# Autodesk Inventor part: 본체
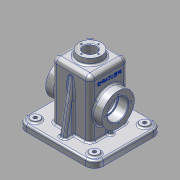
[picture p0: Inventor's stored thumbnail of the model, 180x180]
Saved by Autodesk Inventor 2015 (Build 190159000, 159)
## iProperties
Created: 2016-02
Part Number: 본체
Material: 알루미늄 6061
Document SubType Name: Modeling
Designer: Administrator
Density: 2.7 g/cm^3
Appearance: 알루미늄 - 평지
Mass: 883.249 g
Surface Area: 914.012 cm^2
Volume: 327.129 cm^3
Author: Administrator
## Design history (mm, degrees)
sketch "스케치7"
  geometry: L1 (32.5, 32.5)-(-32.5, 32.5); L2 (-32.5, 32.5)-(-32.5, -32.5); L3 (-32.5, -32.5)-(32.5, -32.5); L4 (32.5, -32.5)-(32.5, 32.5); L5 (32.5, 32.5)-(-32.5, -32.5); L6 (-32.5, 32.5)-(32.5, -32.5); 1 further point
  constraints: 12 end point, 2 midpoint, 2 parallel, 2 perpendicular, 1 horizontal
  dimensions: "d20" = 65 distance of L2.end L3.end
extrude "돌출6" new body sketch "스케치7" distance "d21" = 110; taper "d22" = 0 deg
fillet "모깎기2" dims "d23" = 8
fillet "모깎기3" dims "d24" = 8
feature "쉘1" dims "d25" = 5
sketch "스케치8"
  geometry: C1 r 20 at (0, 0); 1 further point
  constraints: 1 centre point, 1 coincident
  dimensions: "d26" = 40 diameter of C1
extrude "돌출7" join sketch "스케치8" distance "d27" = 10; taper "d28" = 0 deg
feature "면 기울기2" dims angle "d29" = 5 deg
sketch "스케치9"
  geometry: L1 (65, 57.5)-(-65, 57.5); L2 (-65, 57.5)-(-65, -57.5); L3 (-65, -57.5)-(65, -57.5); L4 (65, -57.5)-(65, 57.5); L5 (65, 57.5)-(-65, -57.5); L6 (-65, 57.5)-(65, -57.5); L7 (27.5, -24.5)-(27.5, 24.5) reference; L8 (24.5, 27.5)-(-24.5, 27.5) reference; L9 (-27.5, 24.5)-(-27.5, -24.5) reference; L10 (-24.5, -27.5)-(24.5, -27.5) reference; L11 (24.5, -32.5)-(-24.5, -32.5) reference; L12 (-32.5, -24.5)-(-32.5, 24.5) reference; L13 (-24.5, 32.5)-(24.5, 32.5) reference; L14 (32.5, 24.5)-(32.5, -24.5) reference; A1 r 3 centre (24.5, -24.5) between (24.5, -27.5) and (27.5, -24.5) reference; A2 r 3 centre (24.5, 24.5) between (27.5, 24.5) and (24.5, 27.5) reference; A3 r 3 centre (-24.5, 24.5) between (-24.5, 27.5) and (-27.5, 24.5) reference; A4 r 3 centre (-24.5, -24.5) between (-27.5, -24.5) and (-24.5, -27.5) reference; A5 r 8 centre (24.5, -24.5) between (24.5, -32.5) and (32.5, -24.5) reference; A6 r 8 centre (-24.5, -24.5) between (-32.5, -24.5) and (-24.5, -32.5) reference; A7 r 8 centre (-24.5, 24.5) between (-24.5, 32.5) and (-32.5, 24.5) reference; A8 r 8 centre (24.5, 24.5) between (32.5, 24.5) and (24.5, 32.5) reference; 1 further point
  constraints: 12 end point, 2 midpoint, 2 parallel, 1 horizontal, 1 perpendicular
  dimensions: "d30" = 130 distance of L2.end L3.end; "d31" = 115 distance of L1.end L2.end
extrude "돌출8" join sketch "스케치9" distance "d32" = 13; taper "d33" = 0 deg
fillet "모깎기4" dims "d34" = 15
sketch "스케치11"
  geometry: L1 (110, 24.5)-(110, 20) reference; L2 (110, 20)-(120, 19.125) reference; L3 (120, 19.125)-(120, -19.125) reference; L4 (120, -19.125)-(110, -20) reference; L5 (110, -20)-(110, -24.5) reference; L6 (102, -32.5)-(13, -32.5) reference; L7 (13, -57.5)-(0, -57.5) reference; L8 (13, 57.5)-(13, 32.5) reference; L9 (0, -27.5)-(102, -27.5) reference; L10 (105, -24.5)-(105, 24.5) reference; L11 (102, 27.5)-(0, 27.5) reference; L12 (13, -32.5)-(13, -57.5) reference; L13 (0, 57.5)-(13, 57.5) reference; L14 (13, 32.5)-(102, 32.5) reference; L15 (98.069, 32.5)-(13, 47.5); L16 (13, 47.5)-(13, 32.5); L17 (13, 32.5)-(98.069, 32.5); L18 (0, 0)-(66.088, 0); L19 (13, -32.5)-(98.069, -32.5); L20 (98.069, -32.5)-(13, -47.5); L21 (13, -47.5)-(13, -32.5); L22 (0, -57.5)-(0, -27.5) reference; L23 (0, 27.5)-(0, 57.5) reference; A1 r 8 centre (102, 24.5) between (110, 24.5) and (102, 32.5) reference; A2 r 8 centre (102, -24.5) between (102, -32.5) and (110, -24.5) reference; A3 r 3 centre (102, -24.5) between (102, -27.5) and (105, -24.5) reference; A4 r 3 centre (102, 24.5) between (105, 24.5) and (102, 27.5) reference
  constraints: 14 end point, 3 symmetric about line, 2 collinear, 1 horizontal, 1 perpendicular, 1 vertical
  dimensions: "d38" = 10 deg angle of L13 L15; "d39" = 10 distance from line of L13 L15.end
extrude "돌출10" join sketch "스케치11" stored distance "d40" = 10; taper "d41" = 0 deg
sketch "스케치12"
  geometry: L1 (65, 42.5)-(65, -42.5) reference; L2 (50, -57.5)-(-50, -57.5) reference; L3 (-65, -42.5)-(-65, 42.5) reference; L4 (-50, 57.5)-(50, 57.5) reference; L5 (24.5, 27.5)-(-24.5, 27.5) reference; L6 (-27.5, 24.5)-(-27.5, -24.5) reference; L7 (-24.5, -27.5)-(24.5, -27.5) reference; L8 (27.5, -24.5)-(27.5, 24.5) reference; L9 (60, -42.5)-(60, 42.5); L10 (50, 52.5)-(-50, 52.5); L11 (-60, 42.5)-(-60, -42.5); L12 (-50, -52.5)-(50, -52.5); A1 r 15 centre (50, 42.5) between (65, 42.5) and (50, 57.5) reference; A2 r 15 centre (50, -42.5) between (50, -57.5) and (65, -42.5) reference; A3 r 15 centre (-50, -42.5) between (-65, -42.5) and (-50, -57.5) reference; A4 r 15 centre (-50, 42.5) between (-50, 57.5) and (-65, 42.5) reference; A5 r 3 centre (24.5, 24.5) between (27.5, 24.5) and (24.5, 27.5) reference; A6 r 3 centre (-24.5, 24.5) between (-24.5, 27.5) and (-27.5, 24.5) reference; A7 r 3 centre (-24.5, -24.5) between (-27.5, -24.5) and (-24.5, -27.5) reference; A8 r 3 centre (24.5, -24.5) between (24.5, -27.5) and (27.5, -24.5) reference; A9 r 10 centre (50, 42.5) between (60, 42.5) and (50, 52.5); A10 r 10 centre (-50, 42.5) between (-50, 52.5) and (-60, 42.5); A11 r 10 centre (-50, -42.5) between (-60, -42.5) and (-50, -52.5); A12 r 10 centre (50, -42.5) between (50, -52.5) and (60, -42.5); 1 further point
  constraints: 8 end point, 8 point on circle, 4 centre point, 7 other
  dimensions: "d42" = 5 distance between parallel lines of L1 L9
extrude "돌출11" cut sketch "스케치12" distance "d43" = 2; taper "d44" = 0 deg
node "작업 평면1"
sketch "스케치13"
  geometry: L1 (24.5, -47)-(24.5, -102); C1 r 27.5 at (24.5, -47)
  constraints: 2 end point, 1 centre point, 1 vertical
  dimensions: "d46" = 55 distance of L1.start L1.end; "d47" = 55 diameter of C1
extrude "돌출12" join sketch "스케치13" stored distance "d48" = 2; taper "d49" = 0 deg
sketch "스케치14"
  geometry: L1 (-24.5, 110)-(-20, 110) reference; L2 (-20, 110)-(-19.125, 120) reference; L3 (-19.125, 120)-(19.125, 120) reference; L4 (19.125, 120)-(20, 110) reference; L5 (20, 110)-(24.5, 110) reference; L6 (32.5, 102)-(32.5, 82.5) reference; L7 (32.5, 82.5)-(47.5, 82.5) reference; L8 (47.5, 82.5)-(47.5, 27.5) reference; L9 (47.5, 27.5)-(32.5, 27.5) reference; L10 (32.5, 27.5)-(32.5, 13) reference; L11 (32.5, 13)-(65, 13) reference; L12 (65, 13)-(65, 2) reference; L13 (65, 2)-(60, 2) reference; L14 (60, 2)-(60, 0) reference; L15 (60, 0)-(27.5, 0) reference; L16 (27.5, 0)-(27.5, 102) reference; L17 (24.5, 105)-(-24.5, 105) reference; L18 (-27.5, 102)-(-27.5, 0) reference; L19 (-27.5, 0)-(-60, 0) reference; L20 (-60, 0)-(-60, 2) reference; L21 (-60, 2)-(-65, 2) reference; L22 (-65, 2)-(-65, 13) reference; L23 (-65, 13)-(-32.5, 13) reference; L24 (-32.5, 13)-(-32.5, 102) reference; L25 (32.5, 13)-(32.5, 37.5); L26 (32.5, 13)-(37.5, 13); L27 (37.5, 13)-(37.5, 37.5); L28 (37.5, 37.5)-(32.5, 37.5); A1 r 8 centre (-24.5, 102) between (-24.5, 110) and (-32.5, 102) reference; A2 r 8 centre (24.5, 102) between (32.5, 102) and (24.5, 110) reference; A3 r 3 centre (24.5, 102) between (27.5, 102) and (24.5, 105) reference; A4 r 3 centre (-24.5, 102) between (-24.5, 105) and (-27.5, 102) reference; 2 further points
  constraints: 8 end point, 2 collinear, 2 point on line, 1 parallel, 1 perpendicular
  dimensions: "d73" = 10 distance between parallel lines of L16 L27; "d74" = 10 distance between parallel lines of L28 L9
extrude "돌출13" join sketch "스케치14" stored distance "d51" = 6; taper "d52" = 0 deg
sketch "스케치15"
  geometry: L1 (-65, -42.5)-(-65, 42.5) reference; L2 (-50, 57.5)-(50, 57.5) reference; L3 (65, 42.5)-(65, -42.5) reference; L4 (50, -57.5)-(-50, -57.5) reference; L5 (-24.5, -27.5)-(24.5, -27.5) reference; L6 (27.5, -24.5)-(27.5, 24.5) reference; L7 (24.5, 27.5)-(-24.5, 27.5) reference; L8 (-27.5, 24.5)-(-27.5, -24.5) reference; L9 (-32.5, -24.5)-(-32.5, 24.5) reference; L10 (-24.5, 32.5)-(-5, 32.5) reference; L11 (-5, 32.5)-(-5, 47.5) reference; L12 (-5, 47.5)-(5, 47.5) reference; L13 (5, 47.5)-(5, 32.5) reference; L14 (5, 32.5)-(24.5, 32.5) reference; L15 (32.5, 24.5)-(32.5, 3) reference; L16 (32.5, 3)-(37.5, 3) reference; L17 (37.5, -3)-(32.5, -3) reference; L18 (32.5, -3)-(32.5, -24.5) reference; L19 (24.5, -32.5)-(5, -32.5) reference; L20 (5, -32.5)-(5, -47.5) reference; L21 (5, -47.5)-(-5, -47.5) reference; L22 (-5, -47.5)-(-5, -32.5) reference; L23 (-5, -32.5)-(-24.5, -32.5) reference; L24 (37.5, 3)-(37.5, -3) reference; C1 r 7.5 at (-50, -42.5); C2 r 7.5 at (-50, 42.5); C3 r 7.5 at (50, 42.5); C4 r 7.5 at (50, -42.5); A1 r 15 centre (-50, 42.5) between (-50, 57.5) and (-65, 42.5) reference; A2 r 15 centre (50, 42.5) between (65, 42.5) and (50, 57.5) reference; A3 r 15 centre (50, -42.5) between (50, -57.5) and (65, -42.5) reference; A4 r 15 centre (-50, -42.5) between (-65, -42.5) and (-50, -57.5) reference; A5 r 3 centre (-24.5, -24.5) between (-27.5, -24.5) and (-24.5, -27.5) reference; A6 r 3 centre (24.5, -24.5) between (24.5, -27.5) and (27.5, -24.5) reference; A7 r 3 centre (24.5, 24.5) between (27.5, 24.5) and (24.5, 27.5) reference; A8 r 3 centre (-24.5, 24.5) between (-24.5, 27.5) and (-27.5, 24.5) reference; A9 r 8 centre (-24.5, -24.5) between (-32.5, -24.5) and (-24.5, -32.5) reference; A10 r 8 centre (-24.5, 24.5) between (-24.5, 32.5) and (-32.5, 24.5) reference; A11 r 8 centre (24.5, 24.5) between (32.5, 24.5) and (24.5, 32.5) reference; A12 r 8 centre (24.5, -24.5) between (24.5, -32.5) and (32.5, -24.5) reference; 1 further point
  constraints: 4 centre point, 4 coincident, 3 equal radius
  dimensions: "d53" = 15 diameter of C1
extrude "돌출14" join sketch "스케치15" distance "d54" = 3; taper "d55" = 0 deg
sketch "스케치16"
  geometry: L1 (25.5, -70)-(74.5, -70) reference; L2 (77.5, -67)-(77.5, -18) reference; L3 (74.5, -15)-(25.5, -15) reference; L4 (22.5, -18)-(22.5, -67) reference; L5 (17.5, -67)-(17.5, -18) reference; L6 (25.5, -10)-(45, -10) reference; L7 (45, -10)-(45, 4.471) reference; L8 (45, 4.471)-(55, 4.471) reference; L9 (55, 4.471)-(55, -10) reference; L10 (55, -10)-(74.5, -10) reference; L11 (82.5, -18)-(82.5, -39.5) reference; L12 (82.5, -39.5)-(87.5, -39.5) reference; L13 (87.5, -45.5)-(82.5, -45.5) reference; L14 (82.5, -45.5)-(82.5, -67) reference; L15 (74.5, -75)-(55, -75) reference; L16 (55, -75)-(55, -89.471) reference; L17 (55, -89.471)-(45, -89.471) reference; L18 (45, -89.471)-(45, -75) reference; L19 (45, -75)-(25.5, -75) reference; L20 (87.5, -39.5)-(87.5, -45.5) reference; C1 r 7.5 at (100, 0) reference; C2 r 7.5 at (0, -85) reference; C3 r 7.5 at (0, 0) reference; C4 r 7.5 at (100, -85) reference; A1 r 3 centre (25.5, -67) between (22.5, -67) and (25.5, -70) reference; A2 r 3 centre (74.5, -67) between (74.5, -70) and (77.5, -67) reference; A3 r 3 centre (74.5, -18) between (77.5, -18) and (74.5, -15) reference; A4 r 3 centre (25.5, -18) between (25.5, -15) and (22.5, -18) reference; A5 r 8 centre (25.5, -67) between (17.5, -67) and (25.5, -75) reference; A6 r 8 centre (25.5, -18) between (25.5, -10) and (17.5, -18) reference; A7 r 8 centre (74.5, -18) between (82.5, -18) and (74.5, -10) reference; A8 r 8 centre (74.5, -67) between (74.5, -75) and (82.5, -67) reference; 1 further point
hole "구멍1" sketch "스케치16" at (0, 0), (100, 0), (100, -85), (0, -85) diameter "d56" = 6; stored, may be unused: countersink angle "d60" = 90 deg, drill point angle "d62" = 118 deg; dims "d57" = 6, "d58" = 4, "d59" = 2, "d61" = 8
hole "구멍2" diameter "d65" = 30; stored, may be unused: countersink angle "d69" = 90 deg, drill point angle "d71" = 118 deg; dims "d63" = 10, "d64" = 10, "d66" = 6, "d67" = 35, "d68" = 17, "d70" = 8
fillet "모깎기11" dims "d80" = 3
hole "구멍3" diameter "d83" = 21; stored, may be unused: countersink angle "d87" = 90 deg, drill point angle "d89" = 118 deg; dims "d81" = 10, "d82" = 10, "d84" = 6, "d85" = 35, "d86" = 17, "d88" = 8
fillet "모깎기12" dims "d90" = 3
chamfer "모따기1" distance "d91" = 1; stored, may be unused: second distance "d92" = 2, angle "d93" = 45 deg
fillet "모깎기13" dims "d94" = 0.3
fillet "모깎기14" dims "d95" = 3
sketch "스케치17"
  geometry: L1 (0, 0)-(0, -14.5); 1 further point
  constraints: 2 end point, 1 coincident, 1 vertical
  dimensions: "d96" = 14.5 distance of L1.start L1.end
hole "구멍4" sketch "스케치17" at (0, -14.5) diameter "d97" = 2.459; stored, may be unused: countersink angle "d101" = 90 deg, drill point angle "d103" = 118 deg; dims "d98" = 7, "d99" = 35, "d100" = 17, "d102" = 9
sketch "스케치18"
  geometry: L1 (0, 0)-(0, 21); C1 r 27.5 at (0, 0) reference; 2 further points
  constraints: 2 end point, 1 coincident, 1 vertical
  dimensions: "d107" = 21 distance of L1.start L1.end
hole "구멍5" sketch "스케치18" at (0, 21) diameter "d108" = 3.242; stored, may be unused: countersink angle "d112" = 90 deg, drill point angle "d114" = 118 deg; dims "d109" = 8, "d110" = 35, "d111" = 17, "d113" = 10
node "작업 평면2"
sketch "스케치19"
  geometry: L1 (43.625, 18)-(5.375, 18) reference; L2 (-8, 0)-(-8, -89) reference; 3 further points
  constraints: 1 other
  dimensions: "d119" = 26 distance from line of L1 point (24.5, -8); "d120" = 32.5 distance from line of point (24.5, -8) L2
feature "엠보싱1" sketch "스케치19" dims "d121" = 0.5, "d122" = 0
fillet "모깎기15" dims "d123" = 3
fillet "모깎기16" dims "d124" = 3
fillet "모깎기17" dims "d125" = 3
fillet "모깎기18" dims "d126" = 3
fillet "모깎기19" dims "d127" = 3
node "솔리드2"
mirror "대칭2"
mirror "대칭3"
pattern_circular "원형 패턴1" dims angle "d105" = 360 deg
pattern_circular "원형 패턴2" dims angle "d116" = 360 deg
mirror "대칭4"
node "절단 모서리 투영2"
node "절단 모서리 투영4"
node "절단 모서리 투영5"
node "절단 모서리 투영6"
node "절단 모서리 투영7"
node "절단 모서리 투영8"
other parameters: "d45" = 15
